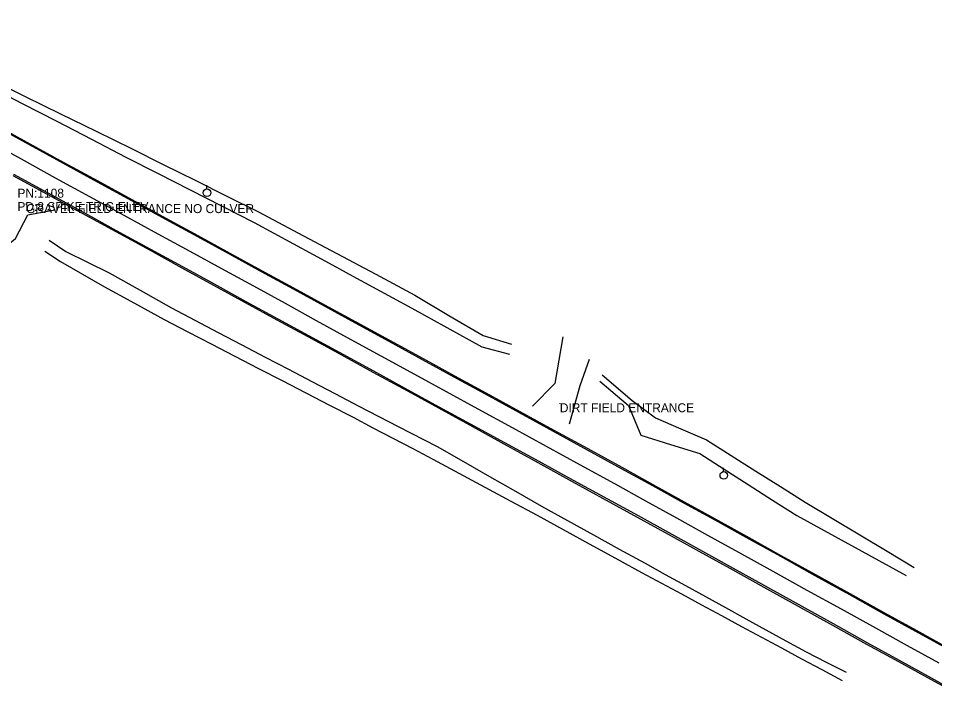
# Model space of a CAD drawing. Extents: x 1411444 to 1458157, y 300965 to 327300.
# Drawn here: x 1456081 to 1456593, y 301762 to 302141 of the extents above; entities that cross this region are included whole.
import ezdxf

# ---------------------------------------------------------------- set-up
doc = ezdxf.new("R2010")
doc.units = 0
for name, color, linetype in [('S_DITCHLINE', 7, 'Continuous'), ('S_DRIVEWAY', 7, 'Continuous'), ('S_EDGE_PAVEMENT', 7, 'Continuous'), ('S_MSC_PT_SYM', 7, 'Continuous'), ('S_PAVEMENT_CROWN', 7, 'Continuous'), ('S_SECONDARY_CTL_ANNOT', 7, 'Continuous'), ('S_SHOULDER', 7, 'Continuous'), ('S_SURVEY_TEXT_ANNOT', 7, 'Continuous'), ('S_UTILITY_POLE', 7, 'Continuous')]:
    doc.layers.add(name, color=color, linetype=linetype)

msp = doc.modelspace()

# ---------------------------------------------------------------- linework, layer by layer
at = {"layer": 'S_DITCHLINE'}
for points in [[(1456004.24, 302141.26), (1456019.52, 302132.77), (1456034.8, 302124.28), (1456050.07, 302115.79), (1456065.35, 302107.3), (1456085.16, 302097.61), (1456104.96, 302087.91), (1456124.76, 302078.22), (1456144.57, 302068.53), (1456162.33, 302059.69), (1456180.09, 302050.85), (1456197.86, 302042.01), (1456215.62, 302033.18), (1456237.44, 302021.54), (1456259.25, 302009.91), (1456281.07, 301998.28), (1456302.88, 301986.64), (1456321.97, 301975.33), (1456341.06, 301964.02), (1456357, 301959.27)], [(1456064.07, 302103.76), (1456083.43, 302093.76), (1456102.78, 302083.77), (1456122.13, 302073.77), (1456141.49, 302063.77), (1456159.39, 302054.63), (1456177.29, 302045.49), (1456195.2, 302036.35), (1456213.1, 302027.22), (1456224.12, 302021.24), (1456235.14, 302015.26), (1456246.16, 302009.28), (1456257.18, 302003.3), (1456268.2, 301997.32), (1456279.22, 301991.34), (1456290.24, 301985.36), (1456301.26, 301979.39), (1456320.83, 301968.56), (1456340.39, 301957.73), (1456355.79, 301953.67)], [(1456098.54, 302017.36), (1456107.95, 302011.1), (1456120.01, 302005.12), (1456132.07, 301999.13), (1456149.49, 301989.34), (1456166.92, 301979.54), (1456180, 301972.67), (1456193.09, 301965.81), (1456206.18, 301958.94), (1456219.27, 301952.07), (1456232.35, 301945.2), (1456245.44, 301938.33), (1456258.53, 301931.46), (1456271.62, 301924.59), (1456293.55, 301913.36), (1456315.49, 301902.12), (1456330.05, 301893.77), (1456344.61, 301885.41), (1456359.16, 301877.06), (1456373.72, 301868.7), (1456388.21, 301860.74), (1456402.7, 301852.79), (1456417.19, 301844.83), (1456431.68, 301836.87), (1456442.92, 301830.68), (1456454.16, 301824.48), (1456465.4, 301818.29), (1456476.64, 301812.1), (1456487.87, 301805.9), (1456499.11, 301799.71), (1456510.35, 301793.52), (1456521.59, 301787.32), (1456532.75, 301781.64), (1456543.91, 301775.97)], [(1456096.21, 302011.17), (1456104.92, 302005.41), (1456117.23, 301998.38), (1456129.54, 301991.35), (1456146.16, 301982.2), (1456162.78, 301973.06), (1456175.98, 301966.23), (1456189.18, 301959.4), (1456202.39, 301952.57), (1456215.59, 301945.74), (1456228.79, 301938.92), (1456242, 301932.09), (1456255.2, 301925.26), (1456268.4, 301918.43), (1456279.54, 301912.6), (1456290.68, 301906.77), (1456301.82, 301900.93), (1456312.96, 301895.1), (1456327.52, 301887.25), (1456342.09, 301879.4), (1456356.65, 301871.55), (1456371.21, 301863.7), (1456385.82, 301855.72), (1456400.42, 301847.74), (1456415.03, 301839.76), (1456429.64, 301831.78), (1456440.81, 301825.74), (1456451.98, 301819.71), (1456463.16, 301813.68), (1456474.33, 301807.64), (1456485.5, 301801.61), (1456496.68, 301795.57), (1456507.85, 301789.54), (1456519.03, 301783.51), (1456530.4, 301777.45), (1456541.78, 301771.39)], [(1456406.23, 301938.56), (1456422.37, 301924.91), (1456429.24, 301908.45), (1456445.72, 301903.29), (1456462.19, 301898.13), (1456475.74, 301889.49), (1456489.29, 301880.84), (1456502.84, 301872.2), (1456516.39, 301863.56), (1456531.7, 301855.17), (1456547, 301846.79), (1456562.3, 301838.41), (1456577.61, 301830.03)], [(1456407.56, 301942.09), (1456424.33, 301927.79), (1456437.35, 301918.11), (1456451.59, 301911.94), (1456465.84, 301905.77), (1456479.67, 301897.07), (1456493.5, 301888.37), (1456507.32, 301879.66), (1456521.15, 301870.96), (1456536.38, 301861.86), (1456551.61, 301852.76), (1456566.85, 301843.66), (1456582.08, 301834.57)]]:
    msp.add_lwpolyline(points, dxfattribs=at)
at = {"layer": 'S_DRIVEWAY'}
for points in [[(1456069.21, 302009.98), (1456079.73, 302018.24), (1456086.57, 302031.54), (1456101.67, 302034.24)], [(1456385.57, 301963.4), (1456383.37, 301950.37), (1456381.17, 301937.34), (1456368.63, 301924.63)], [(1456389.35, 301914.81), (1456395.26, 301936.09), (1456400.51, 301950.94)]]:
    msp.add_lwpolyline(points, dxfattribs=at)
at = {"layer": 'S_EDGE_PAVEMENT'}
for points in [[(1456068.18, 302081.25), (1456087.41, 302070.78), (1456106.44, 302060.37), (1456125.47, 302049.96), (1456144.51, 302039.55), (1456163.54, 302029.14), (1456181.38, 302019.4), (1456199.23, 302009.66), (1456217.07, 301999.92), (1456234.92, 301990.18), (1456252.28, 301980.65), (1456269.64, 301971.12), (1456288.33, 301960.89), (1456307.03, 301950.67), (1456324.67, 301941.09), (1456342.31, 301931.51), (1456361.31, 301921.09), (1456380.31, 301910.67), (1456399.31, 301900.25), (1456418.31, 301889.83), (1456435.72, 301880.23), (1456453.14, 301870.63), (1456470.56, 301861.04), (1456487.97, 301851.44), (1456507.25, 301840.75), (1456526.53, 301830.07), (1456545.8, 301819.38), (1456565.08, 301808.69), (1456582.76, 301798.94), (1456600.45, 301789.19)], [(1456078.61, 302054.21), (1456097.76, 302043.74), (1456116.92, 302033.28), (1456136.08, 302022.82), (1456155.24, 302012.36), (1456173, 302002.64), (1456190.77, 301992.91), (1456208.53, 301983.18), (1456226.29, 301973.45), (1456243.43, 301964.08), (1456260.57, 301954.71), (1456279.77, 301944.27), (1456298.96, 301933.84), (1456316.38, 301924.31), (1456333.8, 301914.78), (1456353, 301904.31), (1456372.2, 301893.84), (1456391.4, 301883.37), (1456410.6, 301872.9), (1456427.76, 301863.46), (1456444.92, 301854.02), (1456462.08, 301844.58), (1456479.24, 301835.14), (1456498.4, 301824.48), (1456517.55, 301813.82), (1456536.71, 301803.17), (1456555.87, 301792.51), (1456573.66, 301782.7), (1456591.44, 301772.88), (1456609.23, 301763.07)]]:
    msp.add_lwpolyline(points, dxfattribs=at)
at = {"layer": 'S_MSC_PT_SYM'}
for points in [[(1456085.65, 302037.48), (1456085.65, 302037.53), (1456085.65, 302037.48), (1456085.6, 302037.48), (1456085.65, 302037.48), (1456085.65, 302037.43), (1456085.65, 302037.48), (1456085.7, 302037.48)], [(1456383.95, 301926.24), (1456383.95, 301926.29), (1456383.95, 301926.24), (1456383.9, 301926.24), (1456383.95, 301926.24), (1456383.95, 301926.19), (1456383.95, 301926.24), (1456384, 301926.24)]]:
    msp.add_lwpolyline(points, dxfattribs=at)
at = {"layer": 'S_PAVEMENT_CROWN'}
msp.add_lwpolyline([(1456063.65, 302073.16), (1456082.83, 302062.71), (1456101.97, 302052.26), (1456121.1, 302041.8), (1456140.24, 302031.35), (1456159.37, 302020.89), (1456177.14, 302011.19), (1456194.91, 302001.49), (1456212.67, 301991.78), (1456230.44, 301982.08), (1456247.75, 301972.52), (1456265.06, 301962.95), (1456283.91, 301952.68), (1456302.76, 301942.41), (1456320.48, 301932.8), (1456338.19, 301923.19), (1456357.25, 301912.74), (1456376.31, 301902.29), (1456395.37, 301891.84), (1456414.43, 301881.39), (1456431.77, 301871.8), (1456449.1, 301862.2), (1456466.43, 301852.6), (1456483.77, 301843.01), (1456502.91, 301832.46), (1456522.05, 301821.92), (1456541.2, 301811.38), (1456560.34, 301800.83), (1456578.09, 301791.02), (1456595.83, 301781.22)], dxfattribs=at)
at = {"layer": 'S_SHOULDER'}
for points in [[(1456068.45, 302081.7), (1456087.66, 302071.18), (1456106.71, 302060.8), (1456125.75, 302050.41), (1456144.8, 302040.02), (1456163.85, 302029.63), (1456181.65, 302019.89), (1456199.46, 302010.15), (1456217.26, 302000.4), (1456235.06, 301990.66), (1456252.49, 301981.2), (1456269.92, 301971.73), (1456288.76, 301961.52), (1456307.6, 301951.31), (1456325.13, 301941.66), (1456342.66, 301932.01), (1456361.63, 301921.64), (1456380.6, 301911.28), (1456399.57, 301900.91), (1456418.54, 301890.54), (1456435.97, 301880.9), (1456453.4, 301871.26), (1456470.83, 301861.61), (1456488.26, 301851.97), (1456507.54, 301841.29), (1456526.82, 301830.6), (1456546.1, 301819.92), (1456565.38, 301809.24), (1456583.06, 301799.48), (1456600.74, 301789.72)], [(1456078.33, 302053.51), (1456097.49, 302043.05), (1456116.65, 302032.6), (1456135.81, 302022.14), (1456154.96, 302011.68), (1456172.69, 302001.97), (1456190.42, 301992.26), (1456208.14, 301982.55), (1456225.87, 301972.84), (1456243.04, 301963.54), (1456260.21, 301954.23), (1456279.47, 301943.67), (1456298.73, 301933.11), (1456316.12, 301923.62), (1456333.52, 301914.14), (1456352.62, 301903.62), (1456371.72, 301893.1), (1456390.83, 301882.58), (1456409.93, 301872.06), (1456427.18, 301862.56), (1456444.42, 301853.05), (1456461.67, 301843.55), (1456478.92, 301834.04), (1456498.04, 301823.46), (1456517.17, 301812.88), (1456536.3, 301802.31), (1456555.42, 301791.73), (1456573.25, 301781.94), (1456591.09, 301772.15), (1456608.92, 301762.36)]]:
    msp.add_lwpolyline(points, dxfattribs=at)
at = {"layer": 'S_UTILITY_POLE'}
for p, q in [((1456186.64, 302046), (1456186.64, 302048.11)), ((1456475.48, 301888.1), (1456475.48, 301890.21))]:
    msp.add_line(p, q, dxfattribs=at)
for centre in [(1456186.76, 302043.86), (1456475.61, 301885.96)]:
    msp.add_circle(centre, 2.13, dxfattribs=at)

# ---------------------------------------------------------------- texts
at = {"layer": 'S_SECONDARY_CTL_ANNOT'}
for s, p in [('PN:1108', (1456080.81, 302041.1)), ('PD:8 SPIKE,TRIG ELEV', (1456080.81, 302033.6))]:
    msp.add_text(s, height=5, dxfattribs=at).set_placement(p)
at = {"layer": 'S_SURVEY_TEXT_ANNOT'}
for s, p in [('GRAVEL FIELD ENTRANCE NO CULVER', (1456085.65, 302032.48)), ('DIRT FIELD ENTRANCE', (1456383.95, 301921.24))]:
    msp.add_text(s, height=5, dxfattribs=at).set_placement(p)

doc.saveas('drawing.dxf')
